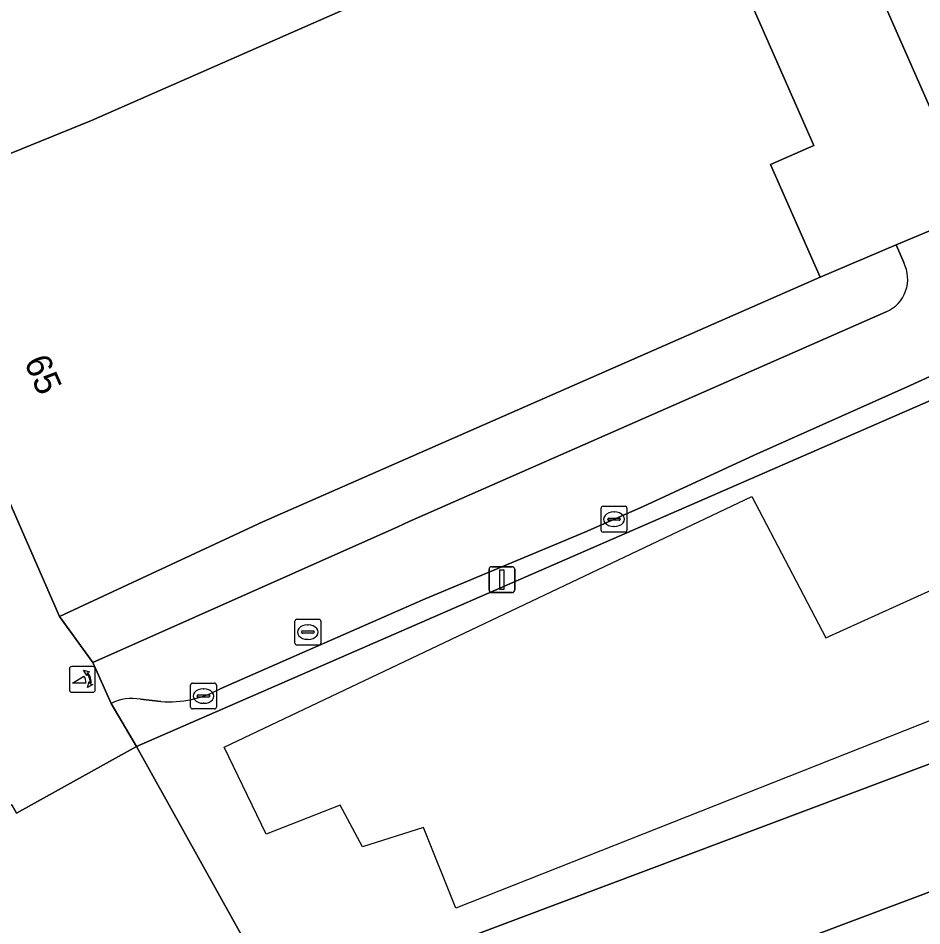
# Model space of a CAD drawing. Extents: x 161881 to 162523, y 381678 to 382381.
# Drawn here: x 162084.3 to 162119.25, y 381984.36 to 382019.48 of the extents above; entities that cross this region are included whole.
import ezdxf

# ---------------------------------------------------------------- set-up
doc = ezdxf.new("R2010")
doc.units = 0
for name, color, linetype in [('IMGEO_Erf', 7, 'Continuous'), ('IMGEO_Kolk', 7, 'Continuous'), ('IMGEO_Lichtmast', 7, 'Continuous'), ('IMGEO_Pand', 7, 'Continuous'), ('IMGEO_Pand_nummerreeks', 7, 'Continuous'), ('IMGEO_Pand_vergunning_verleend', 7, 'Continuous'), ('IMGEO_Poller', 7, 'Continuous'), ('IMGEO_Rijbaan_lokaal_open', 7, 'Continuous'), ('IMGEO_Rioolput', 7, 'Continuous'), ('IMGEO_Voetpad_open', 7, 'Continuous')]:
    doc.layers.add(name, color=color, linetype=linetype)

msp = doc.modelspace()

# ---------------------------------------------------------------- linework, layer by layer
at = {"layer": 'IMGEO_Erf'}
for points in [[(162111.955, 382021.645), (162113.062, 382019.128), (162115.076, 382014.551), (162113.399, 382013.814), (162115.312, 382009.466), (162118.257, 382010.706), (162121.086, 382011.898), (162121.326, 382012.016), (162119.313, 382016.593), (162117.529, 382020.65)], [(162146.312, 381983.042), (162143.669, 381986.685), (162141.59, 381985.176), (162140.681, 381986.429), (162143.067, 381988.153), (162139.459, 381993.132), (162135.939, 381997.989), (162134.482, 382000), (162132.419, 382002.847), (162131.743, 382003.78), (162128.814, 382007.832), (162128.245, 382008.75), (162119.792, 382004.774), (162088.878, 381991.295), (162094.493, 381981.199), (162124.179, 381992.364), (162125.323, 381987.847), (162115.138, 381984.016)]]:
    msp.add_lwpolyline(points, dxfattribs=at)
at = {"layer": 'IMGEO_Kolk'}
for p, q in [((162106.843, 381999.669), (162106.843, 382000.521)), ((162106.918, 382000.595), (162107.77, 382000.595)), ((162107.844, 382000.521), (162107.844, 381999.669)), ((162107.102, 382000.089), (162107.102, 382000.101)), ((162107.54, 382000.052), (162107.142, 382000.052)), ((162107.145, 382000.138), (162107.543, 382000.138)), ((162107.331, 382000.375), (162107.356, 382000.375)), ((162107.586, 382000.101), (162107.586, 382000.089)), ((162107.354, 381999.815), (162107.329, 381999.815)), ((162107.77, 381999.595), (162106.918, 381999.595)), ((162091.043, 381993.751), (162091.895, 381993.751)), ((162090.968, 381992.825), (162090.968, 381993.677)), ((162091.456, 381993.531), (162091.481, 381993.531)), ((162091.969, 381993.677), (162091.969, 381992.825)), ((162091.227, 381993.245), (162091.227, 381993.257)), ((162091.665, 381993.208), (162091.267, 381993.208)), ((162091.27, 381993.294), (162091.668, 381993.294)), ((162091.711, 381993.257), (162091.711, 381993.245)), ((162091.895, 381992.751), (162091.043, 381992.751)), ((162091.479, 381992.971), (162091.454, 381992.971))]:
    msp.add_line(p, q, dxfattribs=at)
for points in [[(162106.843, 381999.669), (162106.843, 382000.521)], [(162106.918, 382000.595), (162107.77, 382000.595)], [(162107.844, 382000.521), (162107.844, 381999.669)], [(162107.77, 381999.595), (162106.918, 381999.595)], [(162091.043, 381993.751), (162091.895, 381993.751)], [(162090.968, 381992.825), (162090.968, 381993.677)], [(162091.969, 381993.677), (162091.969, 381992.825)], [(162091.895, 381992.751), (162091.043, 381992.751)]]:
    msp.add_lwpolyline(points, dxfattribs=at)
for centre, radius, start, end in [((162106.92, 382000.519), 0.0765, 91.552, 178.448), ((162106.92, 382000.519), 0.0765, 91.552, 178.448), ((162107.768, 382000.519), 0.0765, 1.552, 88.448), ((162107.768, 382000.519), 0.0765, 1.552, 88.448), ((162107.142, 382000.098), 0.0403, 85.8775, 175.7526), ((162107.139, 382000.088), 0.0366, 178.938, 274.7102), ((162107.543, 382000.095), 0.043, 264.8664, 352.4533), ((162107.547, 382000.1), 0.0386, 1.7309, 96.639), ((162106.92, 381999.671), 0.0765, 181.552, 268.448), ((162106.92, 381999.671), 0.0765, 181.552, 268.448), ((162107.768, 381999.671), 0.0765, 271.552, 358.448), ((162107.768, 381999.671), 0.0765, 271.552, 358.448), ((162091.045, 381993.675), 0.0765, 91.552, 178.448), ((162091.045, 381993.675), 0.0765, 91.552, 178.448), ((162091.893, 381993.675), 0.0765, 1.552, 88.448), ((162091.893, 381993.675), 0.0765, 1.552, 88.448), ((162091.267, 381993.254), 0.0403, 85.8775, 175.7526), ((162091.264, 381993.244), 0.0366, 178.938, 274.7102), ((162091.668, 381993.251), 0.043, 264.8664, 352.4533), ((162091.672, 381993.256), 0.0386, 1.7309, 96.639), ((162091.045, 381992.827), 0.0765, 181.552, 268.448), ((162091.045, 381992.827), 0.0765, 181.552, 268.448), ((162091.893, 381992.827), 0.0765, 271.552, 358.448), ((162091.893, 381992.827), 0.0765, 271.552, 358.448)]:
    msp.add_arc(centre, radius, start, end, dxfattribs=at)
for centre, major_axis, ratio, start_param, end_param in [((162107.33, 382000.095), (-0.387, 0.002), 0.722429, 4.712389, 7.853982), ((162107.355, 382000.095), (-0.39, 0.002), 0.717154, 1.570796, 4.712389), ((162091.455, 381993.251), (-0.387, 0.002), 0.722429, 4.712389, 7.853982), ((162091.48, 381993.251), (-0.39, 0.002), 0.717154, 1.570796, 4.712389)]:
    msp.add_ellipse(centre, major_axis=major_axis, ratio=ratio, start_param=start_param, end_param=end_param, dxfattribs=at)
at = {"layer": 'IMGEO_Lichtmast'}
for p, q in [((162102.513, 381997.356), (162102.513, 381998.156)), ((162102.513, 381998.156), (162102.513, 381997.356)), ((162102.613, 381998.256), (162103.403, 381998.256)), ((162103.403, 381998.256), (162102.613, 381998.256)), ((162103.503, 381998.156), (162103.503, 381997.356)), ((162103.503, 381997.356), (162103.503, 381998.156)), ((162103.403, 381997.256), (162102.613, 381997.256)), ((162102.613, 381997.256), (162103.403, 381997.256))]:
    msp.add_line(p, q, dxfattribs=at)
msp.add_lwpolyline([(162102.933, 381998.131), (162103.083, 381998.131), (162103.083, 381997.381), (162102.933, 381997.381), (162102.933, 381998.131)], dxfattribs=at)
for centre, start, end in [((162102.613, 381998.156), 90, 180), ((162102.613, 381998.156), 90, 180), ((162103.403, 381998.156), 0, 90), ((162103.403, 381998.156), 360, 90), ((162102.613, 381997.356), 180, 270), ((162102.613, 381997.356), 180, 270), ((162103.403, 381997.356), 270, 0), ((162103.403, 381997.356), 270, 0)]:
    msp.add_arc(centre, 0.1, start, end, dxfattribs=at)
at = {"layer": 'IMGEO_Pand'}
for points in [[(162108.51, 382024.928), (162105.694, 382031.331), (162103.968, 382030.577), (162101.461, 382029.482), (162098.962, 382028.391), (162096.464, 382027.3), (162093.965, 382026.209), (162091.618, 382025.184), (162089.288, 382024.167), (162084.309, 382021.993), (162076.155, 382018.699), (162078.98, 382012.213), (162087.135, 382015.525)], [(162123.943, 382025.832), (162120.71, 382021.064), (162118.724, 382022.411), (162117.529, 382020.65), (162119.313, 382016.593), (162121.326, 382012.016), (162126.891, 382016.153), (162130.475, 382021.4)], [(162087.135, 382015.525), (162078.98, 382012.213), (162081.094, 382007.361), (162083.946, 382000.814), (162085.897, 381996.336), (162093.793, 382000), (162115.312, 382009.466), (162113.399, 382013.814), (162115.076, 382014.551), (162113.062, 382019.128), (162111.955, 382021.645), (162110.278, 382020.908), (162108.51, 382024.928)], [(162112.686, 381977.996), (162116.818, 381979.55), (162115.138, 381984.016), (162125.323, 381987.847), (162124.179, 381992.364), (162094.493, 381981.199), (162078.888, 381975.33), (162080.448, 381972.475), (162080.234, 381972.356), (162084.224, 381965.182), (162091.602, 381969.28), (162103.707, 381974.071), (162106.111, 381975.02), (162105.938, 381975.458)], [(162088.878, 381991.295), (162084.239, 381988.715), (162084.06, 381989.037), (162074.163, 381983.415), (162078.888, 381975.33), (162094.493, 381981.199)]]:
    msp.add_lwpolyline(points, close=True, dxfattribs=at)
at = {"layer": 'IMGEO_Pand_vergunning_verleend'}
msp.add_lwpolyline([(162092.271, 381991.269), (162112.67, 382000.971), (162115.53, 381995.498), (162119.635, 381997.363), (162121.376, 381993.01), (162101.226, 381985.05), (162099.983, 381988.159), (162097.619, 381987.413), (162096.749, 381989.03), (162093.888, 381987.91)], close=True, dxfattribs=at)
at = {"layer": 'IMGEO_Poller'}
for p, q in [((162086.287, 381994.301), (162086.287, 381993.494)), ((162086.287, 381994.301), (162086.287, 381993.494)), ((162087.189, 381994.396), (162086.381, 381994.396)), ((162087.189, 381994.396), (162086.381, 381994.396)), ((162087.283, 381993.494), (162087.283, 381994.301)), ((162087.283, 381993.494), (162087.283, 381994.301)), ((162086.381, 381993.399), (162087.189, 381993.399)), ((162086.381, 381993.399), (162087.189, 381993.399))]:
    msp.add_line(p, q, dxfattribs=at)
for points in [[(162086.966, 381994.125), (162086.954, 381994.052), (162086.829, 381994.257)], [(162086.829, 381994.257), (162087.06, 381994.191), (162086.989, 381994.159)], [(162086.922, 381993.752), (162086.409, 381993.752), (162086.839, 381994.027)], [(162086.982, 381993.58), (162087.048, 381993.811), (162087.078, 381993.743)], [(162087.114, 381993.716), (162087.186, 381993.705), (162086.982, 381993.58)]]:
    msp.add_lwpolyline(points, dxfattribs=at)
for centre, radius, start, end in [((162086.381, 381994.301), 0.0946, 90, 180), ((162086.381, 381994.301), 0.0946, 90, 180), ((162086.608, 381993.812), 0.476, 351.7527, 41.1691), ((162086.608, 381993.812), 0.516, 349.3569, 42.2912), ((162087.189, 381994.301), 0.0946, 0, 90), ((162087.189, 381994.301), 0.0946, 0, 90), ((162086.594, 381993.802), 0.332, 351.3247, 42.4854), ((162086.381, 381993.494), 0.0946, 180, 270), ((162086.381, 381993.494), 0.0946, 180, 270), ((162087.189, 381993.494), 0.0946, 270, 0), ((162087.189, 381993.494), 0.0946, 270, 0)]:
    msp.add_arc(centre, radius, start, end, dxfattribs=at)
at = {"layer": 'IMGEO_Rijbaan_lokaal_open'}
for points in [[(162121.086, 382011.898), (162118.257, 382010.706), (162118.549, 382010.023)], [(162092.114, 381993.53), (162100.046, 381997.014), (162106.212, 381999.596), (162108.469, 382000.584), (162112.758, 382002.577), (162118.799, 382005.274), (162125.921, 382008.53), (162130.863, 382010.899)], [(162117.865, 382008.115), (162099.424, 382000), (162098.981, 381999.805), (162087.193, 381994.544), (162087.895, 381992.959)], [(162089.035, 381993.127), (162089.824, 381993.035)]]:
    msp.add_lwpolyline(points, dxfattribs=at)
for centre, radius, start, end in [((162117.305, 382009.392), 1.395, 293.6742, 26.8813), ((162090.092, 381997.34), 4.314, 266.44, 297.9545), ((162088.692, 381991.501), 1.661, 78.093, 118.6735)]:
    msp.add_arc(centre, radius, start, end, dxfattribs=at)
at = {"layer": 'IMGEO_Rioolput'}
for p, q in [((162095.081, 381996.226), (162095.933, 381996.226)), ((162095.006, 381995.3), (162095.006, 381996.152)), ((162095.494, 381996.006), (162095.519, 381996.006)), ((162096.007, 381996.152), (162096.007, 381995.3)), ((162095.265, 381995.72), (162095.265, 381995.732)), ((162095.703, 381995.683), (162095.305, 381995.683)), ((162095.308, 381995.769), (162095.706, 381995.769)), ((162095.749, 381995.732), (162095.749, 381995.72)), ((162095.933, 381995.226), (162095.081, 381995.226)), ((162095.517, 381995.446), (162095.492, 381995.446))]:
    msp.add_line(p, q, dxfattribs=at)
for points in [[(162095.081, 381996.226), (162095.933, 381996.226)], [(162095.006, 381995.3), (162095.006, 381996.152)], [(162096.007, 381996.152), (162096.007, 381995.3)], [(162095.933, 381995.226), (162095.081, 381995.226)]]:
    msp.add_lwpolyline(points, dxfattribs=at)
for centre, radius, start, end in [((162095.083, 381996.15), 0.0765, 91.552, 178.448), ((162095.083, 381996.15), 0.0765, 91.552, 178.448), ((162095.931, 381996.15), 0.0765, 1.552, 88.448), ((162095.931, 381996.15), 0.0765, 1.552, 88.448), ((162095.305, 381995.729), 0.0403, 85.8775, 175.7526), ((162095.302, 381995.719), 0.0366, 178.938, 274.7102), ((162095.706, 381995.726), 0.043, 264.8664, 352.4533), ((162095.71, 381995.731), 0.0386, 1.7309, 96.639), ((162095.083, 381995.302), 0.0765, 181.552, 268.448), ((162095.083, 381995.302), 0.0765, 181.552, 268.448), ((162095.931, 381995.302), 0.0765, 271.552, 358.448), ((162095.931, 381995.302), 0.0765, 271.552, 358.448)]:
    msp.add_arc(centre, radius, start, end, dxfattribs=at)
for centre, major_axis, ratio, start_param, end_param in [((162095.493, 381995.726), (-0.387, 0.002), 0.722429, 4.712389, 7.853982), ((162095.518, 381995.726), (-0.39, 0.002), 0.717154, 1.570796, 4.712389)]:
    msp.add_ellipse(centre, major_axis=major_axis, ratio=ratio, start_param=start_param, end_param=end_param, dxfattribs=at)
at = {"layer": 'IMGEO_Voetpad_open'}
for points in [[(162118.549, 382010.023), (162118.257, 382010.706), (162115.312, 382009.466), (162093.793, 382000), (162085.897, 381996.336), (162087.193, 381994.544), (162098.981, 381999.805)], [(162130.863, 382010.899), (162125.921, 382008.53), (162118.799, 382005.274), (162112.758, 382002.577), (162108.469, 382000.584), (162106.212, 381999.596), (162100.046, 381997.014), (162092.114, 381993.53)], [(162098.981, 381999.805), (162099.424, 382000), (162117.865, 382008.115)], [(162087.895, 381992.959), (162088.878, 381991.295), (162119.792, 382004.774)], [(162089.824, 381993.035), (162089.035, 381993.127)]]:
    msp.add_lwpolyline(points, dxfattribs=at)
msp.add_lwpolyline([(162087.895, 381992.959), (162087.193, 381994.544), (162085.897, 381996.336), (162083.946, 382000.814), (162064.377, 381995.878), (162067.605, 381989.931), (162071.825, 381982.158), (162074.163, 381983.415), (162084.06, 381989.037), (162084.239, 381988.715), (162088.878, 381991.295)], close=True, dxfattribs=at)
for centre, radius, start, end in [((162117.305, 382009.392), 1.395, 293.6742, 26.8813), ((162090.092, 381997.34), 4.314, 266.44, 297.9545), ((162088.692, 381991.501), 1.661, 78.093, 118.6735)]:
    msp.add_arc(centre, radius, start, end, dxfattribs=at)

# ---------------------------------------------------------------- texts
at = {"layer": 'IMGEO_Pand_nummerreeks'}
msp.add_text('65', height=1, rotation=293.7274, dxfattribs=at).set_placement((162084.519, 382006.185))

doc.saveas('drawing.dxf')
